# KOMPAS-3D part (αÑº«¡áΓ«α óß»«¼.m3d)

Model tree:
1. Эскиз:1
2. Операция выдавливания:1
     Толщина стенки 1 = 2; Толщина стенки 2 = 8; Расстояние 1 = 1
3. Эскиз:3
4. Операция выдавливания:2
     Толщина стенки 1 = 2; Толщина стенки 2 = 6; Расстояние 1 = 5
5. Эскиз:4
6. Операция выдавливания:3
     Толщина стенки 1 = 2; Толщина стенки 2 = 6; Расстояние 1 = 1
7. Эскиз:5
8. Эскиз:6
9. Операция выдавливания:4
     Толщина стенки 1 = 2; Толщина стенки 2 = 2.5; Расстояние 1 = 50
10. Эскиз:7
11. Вырезать элемент выдавливания:1
     Толщина стенки 2 = 1.5; Расстояние 1 = 40
12. Эскиз:8
13. Операция выдавливания:5
     Толщина стенки 1 = 2; Толщина стенки 2 = 2.5; Расстояние 1 = 50
14. Эскиз:9
15. Вырезать элемент выдавливания:2
     Толщина стенки 2 = 1.5; Расстояние 1 = 40
16. Эскиз:10
17. Операция выдавливания:6
     Толщина стенки 1 = 2; Толщина стенки 2 = 2.5; Расстояние 1 = 10
18. Эскиз:11
19. Операция выдавливания:7
     Толщина стенки 1 = 2; Толщина стенки 2 = 6; Расстояние 1 = 1
20. Эскиз:12
21. Операция выдавливания:8
     Толщина стенки 1 = 2; Толщина стенки 2 = 6; Расстояние 1 = 5
22. Эскиз:13
23. Операция выдавливания:9
     Толщина стенки 1 = 2; Толщина стенки 2 = 8; Расстояние 1 = 1
24. Эскиз:14
25. Вырезать элемент выдавливания:3
     Толщина стенки 2 = 1.5; Расстояние 1 = 23
26. Эскиз:15
27. Вырезать элемент выдавливания:4
     Толщина стенки 2 = 1.5; Расстояние 1 = 1
